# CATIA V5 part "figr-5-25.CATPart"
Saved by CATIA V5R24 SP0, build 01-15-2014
Part number: Part2
Bounding box of the stored display mesh (mm): x -75 to 75, y -62.5 to 62.5, z 0 to 20
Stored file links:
  D:\KAVITA\CATIA V5-6R2014 Project_ Kavita\CATIA V5-6R2014_partfiles\Partfiles\c05_catia_v5-6r2014_prt\figr-5-25.CATPart
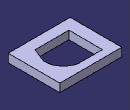
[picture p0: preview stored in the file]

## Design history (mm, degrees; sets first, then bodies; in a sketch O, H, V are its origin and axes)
Body1 (main body)
  Sketch1 on xy-plane, origin (0, 0, 0), H (1, 0, 0), V (0, 1, 0)
    line L1 (-75, 62.5) -> (75, 62.5)
    line L2 (75, 62.5) -> (75, -62.5)
    line L3 (75, -62.5) -> (-75, -62.5)
    line L4 (-75, -62.5) -> (-75, 62.5)
    axis line L5 (75, -62.5) -> (-75, 62.5)
    length L3 = 150
    length L2 = 125
    horizontal: L1 H, L3 H
    vertical: L2 V, L4 V
    midpoint: O L5
  Pad1: profile Sketch1, direction (0, 0, 1), length 20
  Sketch2 on face of Pad1, origin (0, 0, 20), H (1, 0, 0), V (0, 1, 0)
    point P1 (-46.6075, -37.2048)
    line L1 (-46.6075, -37.2048) -> (35.3732, -37.2048)
    point P2 (35.3732, -37.2048)
    point P3 (48.2962, -4.0895)
    line L2 (48.2962, -4.0895) -> (48.2962, 0)
    point P4 (48.2962, 0)
    arc A1 centre (3.919, 0) radius 44.3773 from (48.2962, 0) to (9.9309, 43.9682) ccw
    point P5 (3.919, 0)
    point P6 (9.9309, 43.9682)
    line L3 (9.9309, 43.9682) -> (-46.6075, 43.9682)
    point P7 (-46.6075, 43.9682)
    line L4 (-46.6075, 43.9682) -> (-46.6075, -37.2048)
    line L5 (35.3732, -37.2048) -> (48.2962, -4.0895)
    horizontal: L1 H, L3 H
    coincidence: P4 H
    vertical: L2 V, L4 V
    tangency: A1 L2
    fix: P1, P2, P3, P4, P5, P6, P7, L1, L2, A1, L3, L4, L5
  Pocket1: profile Sketch2, direction (0, 0, -1), through (limit type 3)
